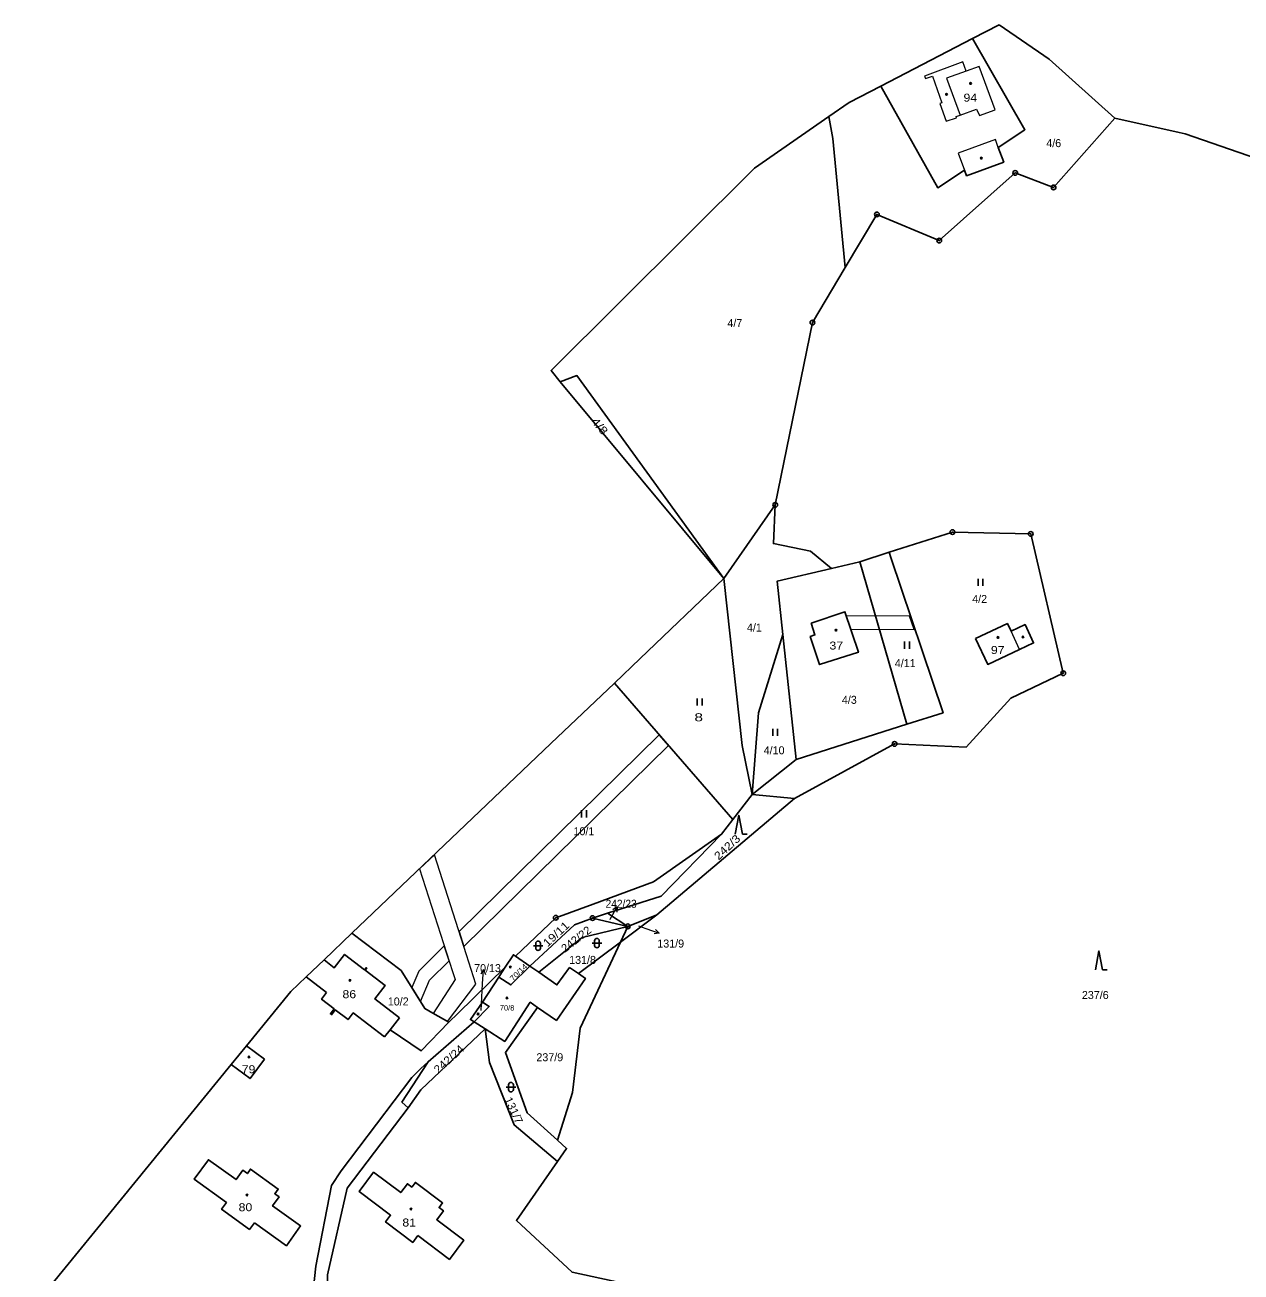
# Model space of a CAD drawing. Extents: x -632162 to -629607, y -1101195 to -1098670.
# Drawn here: x -631918.3 to -631660, y -1098935.2 to -1098670.2 of the extents above; entities that cross this region are included whole.
import ezdxf
from ezdxf.enums import TextEntityAlignment as Align

# ---------------------------------------------------------------- set-up
doc = ezdxf.new("R2010")
doc.units = 0
doc.header["$LTSCALE"] = 0.68
for name, color, linetype, lineweight in [('1', 7, 'Continuous', 25), ('13', 7, 'Continuous', 13), ('3', 7, 'Continuous', 25), ('4', 7, 'Continuous', 13), ('5', 7, 'Continuous', 25), ('7', 7, 'Continuous', 13), ('8', 7, 'Continuous', 25)]:
    doc.layers.add(name, color=color, linetype=linetype, lineweight=lineweight)
doc.layers.add('2', color=7, linetype='Continuous')

msp = doc.modelspace()

# ---------------------------------------------------------------- linework, layer by layer
at = {"layer": '1'}
for p, q in [((-631717.04, -1098673.07), (-631711.43, -1098670.17)), ((-631736.55, -1098683.17), (-631717.04, -1098673.07)), ((-631734.77, -1098782.19), (-631741.02, -1098784.27)), ((-631757.33, -1098799.7), (-631754.53, -1098826.28)), ((-631848.86, -1098863.16), (-631806.61, -1098822.88)), ((-631797.76, -1098859.94), (-631794.58, -1098858.93)), ((-631790.28, -1098861.7), (-631797.76, -1098859.94)), ((-631854.8, -1098868.82), (-631848.86, -1098863.16)), ((-631848.86, -1098863.16), (-631838.39, -1098871.05)), ((-631814.11, -1098868.06), (-631811.09, -1098870.15)), ((-631858.57, -1098872.42), (-631854.8, -1098868.82)), ((-631861.87, -1098875.57), (-631858.57, -1098872.42)), ((-631858.57, -1098872.42), (-631854.24, -1098875.75)), ((-631871.29, -1098887.11), (-631861.87, -1098875.57)), ((-631840.76, -1098883.68), (-631838.79, -1098881.12)), ((-631841.93, -1098885.21), (-631840.76, -1098883.68)), ((-631820.58, -1098883.49), (-631834.27, -1098896.44)), ((-631822.94, -1098881.98), (-631820.58, -1098883.49)), ((-631874.52, -1098891.07), (-631871.29, -1098887.11)), ((-631867.47, -1098889.95), (-631871.29, -1098887.11)), ((-631918.32, -1098944.71), (-631874.52, -1098891.07)), ((-631834.27, -1098896.44), (-631836.9, -1098900.27))]:
    msp.add_line(p, q, dxfattribs=at)
for points in [[(-631711.43, -1098670.17), (-631700.82, -1098677.43), (-631686.85, -1098689.95), (-631673.14, -1098693)], [(-631717.04, -1098673.07), (-631705.92, -1098692.44), (-631711.59, -1098696.22), (-631710.44, -1098699.31), (-631718.32, -1098702.22), (-631718.77, -1098701), (-631724.45, -1098704.78), (-631736.55, -1098683.17)], [(-631747.55, -1098689.63), (-631743.23, -1098686.63), (-631736.55, -1098683.17)], [(-631804.62, -1098745.97), (-631806.57, -1098743.62), (-631763.38, -1098700.61), (-631747.55, -1098689.63)], [(-631747.55, -1098689.63), (-631746.71, -1098694.29), (-631744.11, -1098721.71)], [(-631744.11, -1098721.71), (-631737.37, -1098710.42), (-631724.12, -1098715.99), (-631708, -1098701.61), (-631699.85, -1098704.69), (-631686.85, -1098689.95)], [(-631673.14, -1098693), (-631671.87, -1098693.28), (-631656.74, -1098698.54), (-631656.07, -1098699.15)], [(-631758.98, -1098772.16), (-631751.08, -1098733.4), (-631744.11, -1098721.71)], [(-631804.62, -1098745.97), (-631801.08, -1098744.68), (-631769.85, -1098787.82)], [(-631787.66, -1098804.81), (-631769.85, -1098787.82), (-631804.62, -1098745.97)], [(-631747.04, -1098785.67), (-631751.47, -1098781.97), (-631759.37, -1098780.36), (-631758.98, -1098772.16), (-631769.85, -1098787.82)], [(-631754.89, -1098834.54), (-631733.62, -1098822.94), (-631718.39, -1098823.62), (-631708.94, -1098813.25), (-631697.81, -1098807.93), (-631704.7, -1098778.31), (-631721.32, -1098777.92), (-631734.77, -1098782.19), (-631734.42, -1098783.3), (-631723.32, -1098816.31), (-631731.05, -1098818.73)], [(-631757.33, -1098799.7), (-631758.53, -1098788.34), (-631747.04, -1098785.67)], [(-631731.05, -1098818.73), (-631741.02, -1098784.27), (-631747.04, -1098785.67)], [(-631769.85, -1098787.82), (-631765.98, -1098823.27), (-631763.85, -1098833.71)], [(-631763.85, -1098833.71), (-631762.54, -1098816.35), (-631757.33, -1098799.7)], [(-631806.61, -1098822.88), (-631793.13, -1098810.02), (-631787.66, -1098804.81)], [(-631793.13, -1098810.02), (-631767.95, -1098839.01), (-631763.85, -1098833.71)], [(-631731.05, -1098818.73), (-631754.53, -1098826.28), (-631763.85, -1098833.71), (-631754.89, -1098834.54)], [(-631754.89, -1098834.54), (-631784.11, -1098859.23), (-631791.85, -1098865.05), (-631800.41, -1098883.3), (-631802.02, -1098896.99), (-631805.18, -1098907.15)], [(-631767.95, -1098839.01), (-631770.35, -1098842.11), (-631783.17, -1098855.32), (-631794.58, -1098858.93), (-631790.28, -1098861.7), (-631784.11, -1098859.23)], [(-631814.11, -1098868.06), (-631805.59, -1098859.89), (-631797.64, -1098856.97), (-631784.85, -1098852.27), (-631770.35, -1098842.11)], [(-631811.09, -1098870.15), (-631801.6, -1098861.38), (-631797.76, -1098859.94)], [(-631790.28, -1098861.7), (-631799.99, -1098864.05), (-631809.19, -1098871.47)], [(-631800.76, -1098871.75), (-631791.85, -1098865.05), (-631790.28, -1098861.7)], [(-631838.79, -1098881.12), (-631843.99, -1098877.12), (-631841.81, -1098874.28), (-631846.05, -1098871.02), (-631845.73, -1098870.6), (-631845.87, -1098870.5), (-631846.19, -1098870.92), (-631850.44, -1098867.65), (-631852.62, -1098870.5), (-631854.8, -1098868.82)], [(-631816.3, -1098870.35), (-631814.57, -1098867.74), (-631814.11, -1098868.06)], [(-631816.3, -1098870.35), (-631826.36, -1098880.19), (-631828.28, -1098882.07)], [(-631811.09, -1098870.15), (-631815.1, -1098874.15), (-631817.64, -1098872.53)], [(-631817.64, -1098872.53), (-631816.95, -1098871.33), (-631816.3, -1098870.35)], [(-631800.76, -1098871.75), (-631802.65, -1098870.46), (-631805.32, -1098874.16), (-631809.19, -1098871.47), (-631811.09, -1098870.15)], [(-631838.39, -1098871.05), (-631833.4, -1098879.16), (-631831.72, -1098880.12), (-631828.28, -1098882.07)], [(-631822.94, -1098881.98), (-631823.69, -1098881.5), (-631821.17, -1098877.81), (-631817.64, -1098872.53)], [(-631809.44, -1098878.91), (-631805.43, -1098881.7), (-631799.27, -1098872.76), (-631800.76, -1098871.75)], [(-631854.24, -1098875.75), (-631855.33, -1098877.18), (-631852.64, -1098879.26), (-631853.45, -1098880.32), (-631853.21, -1098880.5), (-631852.4, -1098879.44), (-631849.7, -1098881.51), (-631848.6, -1098880.09), (-631841.93, -1098885.21)], [(-631821.17, -1098877.81), (-631819.72, -1098878.76), (-631822.94, -1098881.98)], [(-631820.58, -1098883.49), (-631816.42, -1098886.16), (-631810.99, -1098877.83), (-631809.44, -1098878.91)], [(-631805.18, -1098907.15), (-631811.63, -1098901.29), (-631816.26, -1098888.48), (-631809.44, -1098878.91)], [(-631850.34, -1099048.98), (-631838.61, -1099016.51), (-631839.84, -1099003.71), (-631848.05, -1098984.13), (-631850.14, -1098972.45), (-631857.33, -1098950.74), (-631857.87, -1098946.44), (-631856.53, -1098933.93), (-631853.21, -1098916.79), (-631851.18, -1098913.62), (-631836.18, -1098893.82), (-631834.25, -1098891.87), (-631832.69, -1098890.51), (-631822.94, -1098881.98)], [(-631828.28, -1098882.07), (-631834.2, -1098888.17), (-631840.76, -1098883.68)], [(-631805.21, -1098911.68), (-631814.43, -1098903.89), (-631819.63, -1098890.66), (-631820.58, -1098883.49)], [(-631874.52, -1098891.07), (-631870.52, -1098894.05), (-631867.47, -1098889.95)], [(-631832.69, -1098890.51), (-631838.26, -1098899.09), (-631836.9, -1098900.27)], [(-631836.9, -1098900.27), (-631849.86, -1098917.35), (-631854.07, -1098935.71), (-631854.14, -1098946.66), (-631853.44, -1098950.94)], [(-631805.18, -1098907.15), (-631803.29, -1098908.87), (-631805.21, -1098911.68)], [(-631751.13, -1098984.71), (-631755.76, -1098984.2), (-631768.22, -1098976.36), (-631769.31, -1098963.09), (-631783.22, -1098952.7), (-631784.58, -1098946.17), (-631782.47, -1098939.42), (-631802.1, -1098935.2), (-631813.94, -1098924.18), (-631805.21, -1098911.68)]]:
    msp.add_lwpolyline(points, dxfattribs=at)
for points in [[(-631751.37, -1098797.25), (-631750.54, -1098799.78), (-631751.54, -1098800.12), (-631749.55, -1098806.07), (-631741.31, -1098803.46), (-631744.16, -1098794.86)], [(-631716.45, -1098800.57), (-631709.66, -1098797.36), (-631708.89, -1098798.99), (-631705.91, -1098797.59), (-631704.08, -1098801.46), (-631707.06, -1098802.87), (-631713.83, -1098806.06)], [(-631869.6, -1098924.68), (-631870.63, -1098926.11), (-631876.57, -1098921.81), (-631875.54, -1098920.38), (-631882.35, -1098915.45), (-631879.36, -1098911.31), (-631873.49, -1098915.52), (-631872.06, -1098913.52), (-631871.08, -1098914.22), (-631870.42, -1098913.29), (-631864.51, -1098917.53), (-631865.28, -1098918.51), (-631864.33, -1098919.19), (-631865.71, -1098921.11), (-631859.79, -1098925.35), (-631862.79, -1098929.58)], [(-631834.9, -1098927.42), (-631835.97, -1098928.85), (-631841.73, -1098924.51), (-631840.66, -1098923.07), (-631847.37, -1098918.03), (-631844.28, -1098913.94), (-631838.52, -1098918.28), (-631837.09, -1098916.4), (-631836.15, -1098917.11), (-631835.4, -1098916.12), (-631829.62, -1098920.48), (-631830.35, -1098921.44), (-631829.43, -1098922.13), (-631830.87, -1098924.05), (-631825.11, -1098928.39), (-631828.17, -1098932.47)]]:
    msp.add_lwpolyline(points, close=True, dxfattribs=at)
at = {"layer": '13'}
for points in [[(-631743.87, -1098795.72), (-631742.93, -1098798.57), (-631729.48, -1098798.61), (-631730.42, -1098795.76)], [(-631783.59, -1098821.01), (-631826.12, -1098862.79), (-631825.1, -1098865.98), (-631781.62, -1098823.27)], [(-631824.52, -1098867.78), (-631831.36, -1098846.47), (-631834.5, -1098849.47), (-631827.52, -1098871.3), (-631826.96, -1098873.02), (-631831.6, -1098880.19), (-631828.56, -1098881.91), (-631822.59, -1098874.02)], [(-631834.33, -1098877.64), (-631832.38, -1098873.13), (-631828.24, -1098869.06), (-631829.26, -1098865.86), (-631834.69, -1098871.2), (-631836.14, -1098874.7)]]:
    msp.add_lwpolyline(points, close=True, dxfattribs=at)
at = {"layer": '3'}
for p, q in [((-631715.861, -1098789.36), (-631715.861, -1098787.86)), ((-631714.86, -1098789.36), (-631714.86, -1098787.86)), ((-631731.481, -1098802.7), (-631731.481, -1098801.2)), ((-631730.48, -1098802.7), (-631730.48, -1098801.2)), ((-631775.521, -1098814.78), (-631775.521, -1098813.28)), ((-631774.52, -1098814.78), (-631774.52, -1098813.28)), ((-631759.491, -1098821.24), (-631759.491, -1098819.74)), ((-631758.49, -1098821.24), (-631758.49, -1098819.74)), ((-631800.081, -1098838.54), (-631800.081, -1098837.04)), ((-631799.08, -1098838.54), (-631799.08, -1098837.04)), ((-631765.95, -1098842.11), (-631764.954, -1098842.11)), ((-631809.841, -1098865.321), (-631809.841, -1098866.322)), ((-631808.839, -1098866.322), (-631808.839, -1098865.321)), ((-631797.831, -1098865.261), (-631795.829, -1098865.261)), ((-631797.331, -1098864.761), (-631797.331, -1098865.762)), ((-631796.329, -1098865.762), (-631796.329, -1098864.761)), ((-631810.341, -1098865.821), (-631808.339, -1098865.821)), ((-631689.47, -1098870.92), (-631688.474, -1098870.92)), ((-631816.091, -1098895.871), (-631814.089, -1098895.871)), ((-631815.591, -1098895.371), (-631815.591, -1098896.372)), ((-631814.589, -1098896.372), (-631814.589, -1098895.371))]:
    msp.add_line(p, q, dxfattribs=at)
for points in [[(-631765.95, -1098842.11), (-631766.7, -1098838.11), (-631767.45, -1098842.11)], [(-631689.47, -1098870.92), (-631690.22, -1098866.92), (-631690.97, -1098870.92)]]:
    msp.add_lwpolyline(points, dxfattribs=at)
for centre, start, end in [((-631809.34, -1098865.3209), 0, 180), ((-631796.83, -1098864.7609), 0, 180), ((-631809.34, -1098866.3209), 180, 359.98789), ((-631796.83, -1098865.7609), 180, 359.98789), ((-631815.09, -1098895.3709), 0, 180), ((-631815.09, -1098896.3709), 180, 359.98789)]:
    msp.add_arc(centre, 0.5, start, end, dxfattribs=at)
at = {"layer": '4'}
for p, q in [((-631719.14, -1098678.01), (-631727.26, -1098681.06)), ((-631718.42, -1098679.99), (-631722.57, -1098681.5)), ((-631718.42, -1098679.99), (-631719.14, -1098678.01)), ((-631715.63, -1098678.97), (-631718.42, -1098679.99)), ((-631712.25, -1098688.23), (-631715.63, -1098678.97)), ((-631727.26, -1098681.06), (-631727.03, -1098681.56)), ((-631727.03, -1098681.56), (-631725.53, -1098681.02)), ((-631725.53, -1098681.02), (-631723.58, -1098686.71)), ((-631722.57, -1098681.5), (-631719.71, -1098689.33)), ((-631723.58, -1098686.71), (-631724.04, -1098686.89)), ((-631724.04, -1098686.89), (-631722.65, -1098690.62)), ((-631722.65, -1098690.62), (-631720.47, -1098689.88)), ((-631720.55, -1098689.64), (-631719.71, -1098689.33)), ((-631720.47, -1098689.88), (-631720.55, -1098689.64)), ((-631719.71, -1098689.33), (-631716.2, -1098688.04)), ((-631716.2, -1098688.04), (-631715.61, -1098689.44)), ((-631715.61, -1098689.44), (-631712.25, -1098688.23)), ((-631712.21, -1098694.53), (-631720.09, -1098697.44)), ((-631711.59, -1098696.22), (-631712.21, -1098694.53)), ((-631720.09, -1098697.44), (-631718.77, -1098701)), ((-631707.06, -1098802.87), (-631708.89, -1098798.99))]:
    msp.add_line(p, q, dxfattribs=at)
at = {"layer": '5'}
for centre in [(-631717.4768, -1098682.6092), (-631722.5868, -1098684.9192), (-631715.1768, -1098698.4692), (-631746.0768, -1098798.7692), (-631711.6468, -1098800.3092), (-631706.3368, -1098800.2092), (-631815.2168, -1098870.3392), (-631849.2668, -1098873.1792), (-631815.9368, -1098876.9092), (-631822.0768, -1098880.3192), (-631870.7268, -1098889.4492), (-631871.1668, -1098918.7992), (-631836.3368, -1098921.7692)]:
    msp.add_circle(centre, 0.175, dxfattribs=at)
at = {"layer": '7'}
for p, q in [((-631792.555, -1098857.545), (-631793.479, -1098858.178)), ((-631783.6, -1098863.176), (-631784.37, -1098862.363)), ((-631820.953, -1098870.893), (-631821.505, -1098871.867))]:
    msp.add_line(p, q, dxfattribs=at)
for points in [[(-631794.04, -1098860.22), (-631794.01, -1098860.17), (-631792.555, -1098857.545), (-631792.603, -1098858.664)], [(-631787.99, -1098861.59), (-631786.42, -1098862.15), (-631783.6, -1098863.176), (-631784.712, -1098863.304)], [(-631821.39, -1098879.6), (-631821.11, -1098873.89), (-631820.953, -1098870.893), (-631820.505, -1098871.919)]]:
    msp.add_lwpolyline(points, dxfattribs=at)
at = {"layer": '8'}
for centre, radius in [((-631708, -1098701.6099), 0.5), ((-631708, -1098701.6099), 0.0303), ((-631699.85, -1098704.6899), 0.5), ((-631699.85, -1098704.6899), 0.0303), ((-631737.37, -1098710.4199), 0.5), ((-631737.37, -1098710.4199), 0.0303), ((-631724.12, -1098715.9899), 0.5), ((-631724.12, -1098715.9899), 0.0303), ((-631751.08, -1098733.3999), 0.5), ((-631751.08, -1098733.3999), 0.0303), ((-631758.98, -1098772.1599), 0.5), ((-631758.98, -1098772.1599), 0.0303), ((-631721.32, -1098777.9199), 0.5), ((-631721.32, -1098777.9199), 0.0303), ((-631704.7, -1098778.3099), 0.5), ((-631704.7, -1098778.3099), 0.0303), ((-631697.81, -1098807.9299), 0.5), ((-631697.81, -1098807.9299), 0.0303), ((-631733.62, -1098822.9399), 0.5), ((-631733.62, -1098822.9399), 0.0303), ((-631805.59, -1098859.8899), 0.5), ((-631805.59, -1098859.8899), 0.0303), ((-631797.76, -1098859.9399), 0.5), ((-631797.76, -1098859.9399), 0.0303), ((-631790.28, -1098861.6999), 0.5), ((-631790.28, -1098861.6999), 0.0303)]:
    msp.add_circle(centre, radius, dxfattribs=at)

# ---------------------------------------------------------------- texts
at = {"layer": '2'}
for s, width, p in [('94', 1.15, (-631717.53, -1098686.47)), ('37', 1.15, (-631746, -1098802.89)), ('97', 1.15, (-631711.71, -1098803.84)), ('8', 1.45, (-631775.22, -1098818.12)), ('242/23', 0.95, (-631791.699, -1098857.75)), ('86', 1.15, (-631849.43, -1098876.97)), ('79', 1.15, (-631870.83, -1098892.91)), ('80', 1.15, (-631871.49, -1098922.23)), ('81', 1.15, (-631836.71, -1098925.48))]:
    msp.add_text(s, height=1.7, dxfattribs=dict(at, width=width)).set_placement(p, align=Align.CENTER)
for s, height, p in [('4/6', 1.7, (-631699.819, -1098696.13)), ('4/7', 1.7, (-631767.549, -1098734.36)), ('4/2', 1.7, (-631715.549, -1098792.99)), ('4/1', 1.7, (-631763.399, -1098799.06)), ('4/11', 1.7, (-631731.35, -1098806.62)), ('4/3', 1.7, (-631743.229, -1098814.42)), ('4/10', 1.7, (-631759.2, -1098825.14)), ('10/1', 1.7, (-631799.6, -1098842.34)), ('131/8', 1.7, (-631799.89, -1098869.68)), ('237/6', 1.7, (-631690.99, -1098877.14)), ('10/2', 1.7, (-631839.04, -1098878.51)), ('70/8', 1.14, (-631815.919, -1098879.58)), ('237/9', 1.7, (-631806.85, -1098890.36))]:
    msp.add_text(s, height=height, dxfattribs=at).set_placement(p, align=Align.CENTER)
for s, height, rotation, width, p in [('4/8', 1.7, 310, 1.25, (-631796.9051, -1098755.9501)), ('242/3', 1.7, 43, 1.15, (-631768.5932, -1098845.5012)), ('19/11', 1.7, 43, 1.15, (-631804.9332, -1098863.9612)), ('242/22', 1.7, 38, 1.05, (-631800.7273, -1098865.0873)), ('70/14', 1.14, 44, 1.15, (-631813.089, -1098871.8839)), ('242/24', 1.7, 42, 1.1, (-631827.7213, -1098890.5397)), ('131/7', 1.7, 295, 1.05, (-631815.2781, -1098901.1483))]:
    msp.add_text(s, height=height, rotation=rotation, dxfattribs=dict(at, width=width)).set_placement(p, align=Align.CENTER)
for s, p in [('131/9', (-631784.01, -1098866.203)), ('70/13', (-631822.92, -1098871.42))]:
    msp.add_text(s, height=1.7, dxfattribs=at).set_placement(p)

doc.saveas('drawing.dxf')
